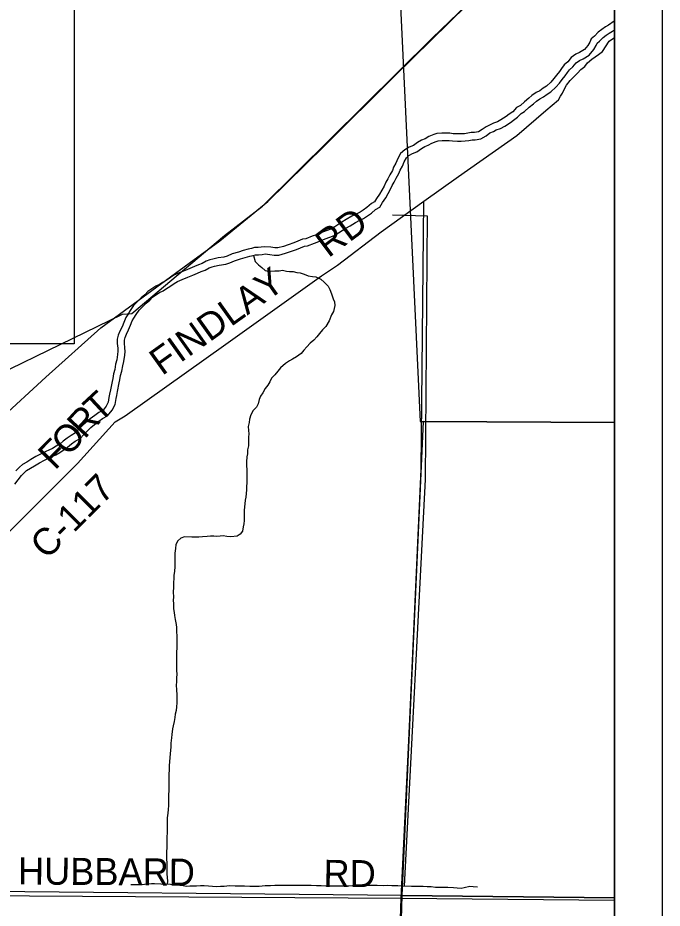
# Model space of a CAD drawing. Extents: x 0 to 34, y 0 to 22.
# Drawn here: x 7.646 to 9, y 14.995 to 16.867 of the extents above; entities that cross this region are included whole.
import ezdxf

# ---------------------------------------------------------------- set-up
doc = ezdxf.new("R2010")
doc.units = 0
for name, color, linetype in [('GM_X_City_Street', 7, 'Continuous'), ('GM_X_County_Road', 7, 'Continuous'), ('GM_X_County_Road_Text', 7, 'Continuous'), ('GM_X_Major_River', 7, 'Continuous'), ('GM_X_Minor_River', 7, 'Continuous'), ('GM_X_Rail_Line', 7, 'Continuous'), ('GM_X_State_Route', 7, 'Continuous'), ('GM_X_Township_Road', 7, 'Continuous'), ('GM_X_US_Route', 7, 'Continuous'), ('SH_Cut_Line', 7, 'Continuous'), ('SH_Data', 7, 'Continuous'), ('SH_Text', 7, 'Continuous')]:
    doc.layers.add(name, color=color, linetype=linetype)

msp = doc.modelspace()

# ---------------------------------------------------------------- linework, layer by layer
at = {"layer": 'GM_X_City_Street'}
for points in [[(8.9, 16.0164), (8.9, 16.9842), (8.447, 16.9667), (8.4914, 16.018), (8.4978, 16.0183)], [(8.9, 15.0171), (8.9, 16.0164), (8.4978, 16.0183), (8.4534, 15.0216)], [(7.4233, 14.1), (8.4275, 14.1), (8.4534, 15.0216), (7.4447, 15.0317), (7.4446, 15.029)], [(8.4275, 14.1), (8.9, 14.1), (8.9, 15.0171), (8.4534, 15.0216)]]:
    msp.add_lwpolyline(points, close=True, dxfattribs=at)
at = {"layer": 'GM_X_County_Road'}
for points in [[(7.6294, 15.7881), (7.7715, 15.9302), (7.8512, 16.0176), (7.8717, 16.0305), (8.0836, 16.1807), (8.2844, 16.3244), (8.3178, 16.3472), (8.4097, 16.4167), (8.4993, 16.4817), (8.5722, 16.5334), (8.6944, 16.6193), (8.7559, 16.6721), (8.7825, 16.6942), (8.7867, 16.7025), (8.7905, 16.7086), (8.7951, 16.7177), (8.7992, 16.7253), (8.8068, 16.7348), (8.8224, 16.7504), (8.8292, 16.758), (8.8376, 16.7645), (8.8433, 16.7721), (8.8524, 16.7801), (8.8665, 16.7899), (8.8744, 16.7964), (8.8885, 16.8177), (8.9, 16.8254)], [(7.447, 15.0225), (8.4514, 15.0162), (8.9, 15.0119)]]:
    msp.add_lwpolyline(points, dxfattribs=at)
at = {"layer": 'GM_X_Major_River'}
for points in [[(8.9, 16.8615), (8.8991, 16.8599), (8.8874, 16.8515), (8.8806, 16.8477), (8.8734, 16.8427), (8.8658, 16.8366), (8.8575, 16.8286), (8.8511, 16.8225), (8.8477, 16.8156), (8.8439, 16.8088), (8.8367, 16.8004), (8.8265, 16.7943), (8.8186, 16.7904), (8.8091, 16.7832), (8.8016, 16.7744), (8.7944, 16.7683), (8.7883, 16.7607), (8.7842, 16.7538), (8.7778, 16.7466), (8.7725, 16.739), (8.7661, 16.7317), (8.757, 16.7233), (8.7502, 16.7187), (8.743, 16.7137), (8.735, 16.7099), (8.7263, 16.7034), (8.7199, 16.6981), (8.7108, 16.6904), (8.7021, 16.6824), (8.6942, 16.6782), (8.6862, 16.6694), (8.6787, 16.6644), (8.6722, 16.6595), (8.6612, 16.6522), (8.6541, 16.648), (8.6457, 16.6453), (8.6389, 16.6418), (8.6306, 16.638), (8.6222, 16.6319), (8.6139, 16.6273), (8.6056, 16.6257), (8.5991, 16.6257), (8.5915, 16.6241), (8.5847, 16.6233), (8.5771, 16.6229), (8.5707, 16.6229), (8.5612, 16.6232), (8.5536, 16.6243), (8.5373, 16.6242), (8.5267, 16.6234), (8.5202, 16.6215), (8.5096, 16.6172), (8.502, 16.6126), (8.4945, 16.6099), (8.4861, 16.6046), (8.4774, 16.5988), (8.4687, 16.595), (8.4592, 16.5896), (8.4505, 16.582), (8.4445, 16.571), (8.4408, 16.5615), (8.4359, 16.5531), (8.4332, 16.5462), (8.4279, 16.5367), (8.4238, 16.5287), (8.4193, 16.5215), (8.4159, 16.5131), (8.411, 16.5047), (8.4065, 16.4964), (8.4001, 16.4872), (8.3959, 16.4804), (8.3891, 16.4765), (8.3796, 16.4681), (8.3721, 16.4624)], [(8.3812, 16.4503), (8.3893, 16.4564), (8.3979, 16.4641), (8.4068, 16.4691), (8.4128, 16.4789), (8.4194, 16.4884), (8.4242, 16.4973), (8.4295, 16.5064), (8.4328, 16.5146), (8.437, 16.5212), (8.4413, 16.5296), (8.447, 16.5398), (8.4496, 16.5465), (8.4544, 16.5548), (8.4583, 16.5645), (8.4626, 16.5724), (8.4681, 16.5772), (8.4755, 16.5814), (8.4847, 16.5855), (8.4944, 16.5919), (8.5012, 16.5963), (8.5086, 16.5989), (8.5164, 16.6036), (8.5252, 16.6071), (8.5294, 16.6084), (8.5379, 16.6091), (8.5525, 16.6091), (8.5598, 16.6081), (8.5704, 16.6077), (8.5776, 16.6077), (8.586, 16.6082), (8.5939, 16.6091), (8.6007, 16.6105), (8.607, 16.6106), (8.6191, 16.6128), (8.6304, 16.6191), (8.6383, 16.6249), (8.6455, 16.6282), (8.6515, 16.6312), (8.6603, 16.6341), (8.6693, 16.6393), (8.6811, 16.6471), (8.6875, 16.6521), (8.6962, 16.6578), (8.7036, 16.666), (8.7109, 16.6699), (8.7208, 16.679), (8.7296, 16.6864), (8.7357, 16.6915), (8.7429, 16.6969), (8.7506, 16.7006), (8.7587, 16.7062), (8.7664, 16.7114), (8.7769, 16.7211), (8.7844, 16.7296), (8.7897, 16.7372), (8.7964, 16.7448), (8.8008, 16.752), (8.8053, 16.7577), (8.8123, 16.7636), (8.8196, 16.7721), (8.8266, 16.7775), (8.8337, 16.7809), (8.8467, 16.7887), (8.8565, 16.8001), (8.8611, 16.8086), (8.8635, 16.8134), (8.868, 16.8176), (8.8759, 16.8252), (8.8825, 16.8306), (8.8886, 16.8348), (8.8956, 16.8387), (8.9, 16.8419)], [(8.3721, 16.4624), (8.3656, 16.4582), (8.3584, 16.4551), (8.3482, 16.4501), (8.3365, 16.4429), (8.3274, 16.4375), (8.3122, 16.4275), (8.3043, 16.4229), (8.2963, 16.4199), (8.2865, 16.416), (8.2736, 16.4106), (8.2649, 16.4076), (8.2513, 16.4025), (8.2448, 16.4014), (8.235, 16.3975), (8.2266, 16.3941), (8.2141, 16.3898), (8.2043, 16.3864), (8.1929, 16.3833), (8.1861, 16.3832), (8.1781, 16.3847), (8.1656, 16.3858), (8.1576, 16.3846), (8.1511, 16.3838), (8.1439, 16.3838), (8.1375, 16.3822), (8.1303, 16.3807), (8.1197, 16.3779), (8.1098, 16.3745), (8.0966, 16.3706), (8.086, 16.366), (8.0795, 16.3637), (8.067, 16.3621), (8.0564, 16.3598), (8.0499, 16.3582), (8.042, 16.3551), (8.034, 16.3505), (8.0261, 16.3478), (8.0177, 16.3444), (8.0079, 16.3402), (7.9977, 16.3359), (7.9852, 16.3309), (7.9745, 16.3256), (7.967, 16.321), (7.9579, 16.3148), (7.9507, 16.3106), (7.9443, 16.3064), (7.9367, 16.303), (7.9303, 16.2987), (7.9197, 16.2915), (7.9132, 16.2846), (7.9057, 16.2785), (7.8894, 16.2621), (7.8822, 16.2514), (7.8773, 16.2434), (7.8732, 16.2366), (7.8691, 16.2263), (7.8653, 16.2172), (7.8608, 16.208), (7.8574, 16.1997), (7.8552, 16.1917), (7.8552, 16.1822), (7.8564, 16.1723), (7.8564, 16.1659), (7.856, 16.159), (7.8542, 16.1476), (7.8519, 16.1385), (7.8501, 16.1275), (7.8475, 16.1184), (7.846, 16.1089), (7.8445, 16.1024), (7.8411, 16.0846), (7.8393, 16.0758), (7.8378, 16.069), (7.8363, 16.0587), (7.8322, 16.0504), (7.8254, 16.0423), (7.8163, 16.0374), (7.808, 16.0312), (7.7981, 16.024), (7.7898, 16.0171), (7.7815, 16.0091), (7.7739, 16.0015), (7.7675, 15.9946), (7.7584, 15.9892), (7.7501, 15.9831), (7.7418, 15.9766), (7.7353, 15.9716), (7.727, 15.9663), (7.7194, 15.9617), (7.7115, 15.9582), (7.705, 15.9552), (7.6956, 15.9502), (7.6846, 15.9444), (7.674, 15.9383), (7.6653, 15.9329), (7.6562, 15.9276), (7.6498, 15.9222), (7.6426, 15.9146)], [(7.64, 15.8867), (7.6473, 15.8957), (7.6542, 15.9048), (7.6602, 15.9112), (7.6649, 15.9151), (7.6731, 15.92), (7.6818, 15.9253), (7.6919, 15.9311), (7.7026, 15.9368), (7.7118, 15.9416), (7.7178, 15.9444), (7.7264, 15.9482), (7.735, 15.9534), (7.7441, 15.9592), (7.7511, 15.9646), (7.7592, 15.971), (7.7668, 15.9766), (7.7771, 15.9826), (7.7848, 15.9909), (7.7921, 15.9983), (7.7999, 16.0058), (7.8075, 16.012), (7.8169, 16.019), (7.8244, 16.0246), (7.8351, 16.0304), (7.8449, 16.042), (7.851, 16.0542), (7.8527, 16.0663), (7.8541, 16.0726), (7.856, 16.0816), (7.8593, 16.0993), (7.8609, 16.106), (7.8623, 16.1151), (7.8649, 16.1241), (7.8668, 16.1355), (7.869, 16.1446), (7.8711, 16.1574), (7.8716, 16.1655), (7.8715, 16.1733), (7.8703, 16.1831), (7.8703, 16.1896), (7.8718, 16.1948), (7.8746, 16.2018), (7.8791, 16.2109), (7.8831, 16.2206), (7.8868, 16.2298), (7.8903, 16.2355), (7.895, 16.2432), (7.9012, 16.2524), (7.9158, 16.2672), (7.9236, 16.2735), (7.9296, 16.2799), (7.9387, 16.2861), (7.944, 16.2896), (7.9516, 16.2931), (7.9587, 16.2977), (7.966, 16.302), (7.9751, 16.3082), (7.9819, 16.3123), (7.9914, 16.3171), (8.0034, 16.3219), (8.0138, 16.3262), (8.0236, 16.3304), (8.0314, 16.3336), (8.0403, 16.3367), (8.0485, 16.3414), (8.0545, 16.3437), (8.0598, 16.345), (8.0696, 16.3471), (8.0831, 16.3489), (8.0915, 16.3519), (8.1017, 16.3563), (8.1145, 16.36), (8.1241, 16.3634), (8.1338, 16.3659), (8.1409, 16.3674), (8.1458, 16.3686), (8.1521, 16.3686), (8.1596, 16.3696), (8.166, 16.3705), (8.1761, 16.3697), (8.1847, 16.3681), (8.195, 16.3681), (8.2088, 16.3719), (8.2191, 16.3755), (8.232, 16.3799), (8.2406, 16.3835), (8.249, 16.3867), (8.2553, 16.3879), (8.27, 16.3933), (8.2791, 16.3965), (8.2922, 16.402), (8.3018, 16.4057), (8.3109, 16.4092), (8.3202, 16.4146), (8.3354, 16.4246), (8.3443, 16.4299), (8.3555, 16.4368), (8.3647, 16.4413), (8.3728, 16.4448), (8.3812, 16.4503)]]:
    msp.add_lwpolyline(points, dxfattribs=at)
at = {"layer": 'GM_X_Minor_River'}
for p, q in [((8.4334, 16.4525), (8.5064, 16.4504)), ((8.5064, 16.4504), (8.5023, 15.8958)), ((8.5023, 15.8962), (8.4583, 15.0418))]:
    msp.add_line(p, q, dxfattribs=at)
for points in [[(8.1417, 16.3676), (8.1448, 16.3545), (8.152, 16.3474), (8.1593, 16.3421), (8.1661, 16.3357), (8.1733, 16.3346), (8.1866, 16.335), (8.1954, 16.3351), (8.2022, 16.3362), (8.2109, 16.3344), (8.2174, 16.3337), (8.225, 16.3337), (8.2329, 16.3318), (8.2398, 16.3311), (8.2481, 16.3281), (8.2565, 16.3244), (8.2652, 16.3233), (8.2724, 16.3222), (8.2827, 16.3177), (8.2899, 16.3109), (8.2983, 16.3026), (8.3021, 16.2958), (8.3052, 16.2867), (8.3087, 16.2761), (8.3117, 16.2696), (8.3125, 16.262), (8.3095, 16.2495), (8.3054, 16.2423), (8.3005, 16.2297), (8.2937, 16.2183), (8.2865, 16.2107), (8.2801, 16.2034), (8.2744, 16.1966), (8.268, 16.1893), (8.2604, 16.1832), (8.2536, 16.1752), (8.2472, 16.1679), (8.2419, 16.1611), (8.2321, 16.1542), (8.2234, 16.1496), (8.2169, 16.1461), (8.2086, 16.1404), (8.198, 16.1309), (8.1924, 16.124), (8.1863, 16.1164), (8.1795, 16.1091), (8.1761, 16.1019), (8.1716, 16.0947), (8.1659, 16.0874), (8.1614, 16.0787), (8.1565, 16.0718), (8.1535, 16.0642), (8.1516, 16.0551), (8.1479, 16.0482), (8.1407, 16.0414), (8.1358, 16.0322), (8.1332, 16.0231), (8.1321, 16.0159), (8.1306, 16.0079), (8.131, 15.9995), (8.1314, 15.9923), (8.131, 15.9855), (8.1311, 15.9737), (8.1307, 15.9669), (8.1292, 15.9585), (8.1289, 15.9506), (8.1278, 15.9437), (8.1271, 15.9335), (8.1272, 15.9092), (8.1276, 15.9023), (8.1272, 15.8898), (8.1269, 15.8811), (8.1265, 15.8746), (8.1258, 15.867), (8.1251, 15.8591), (8.124, 15.8526), (8.1232, 15.845), (8.1221, 15.8317), (8.1222, 15.8169), (8.1218, 15.8101), (8.1211, 15.8032), (8.12, 15.7968), (8.1181, 15.788), (8.1136, 15.7812), (8.1072, 15.7773), (8.0939, 15.7761), (8.0855, 15.7765), (8.078, 15.7776), (8.0715, 15.7775), (8.0647, 15.7767), (8.0582, 15.7771), (8.051, 15.7771), (8.0442, 15.7766), (8.0343, 15.7758), (8.0264, 15.7754), (8.0119, 15.7753), (7.9968, 15.776), (7.9892, 15.7729), (7.9824, 15.7676), (7.9786, 15.76), (7.9775, 15.7516)], [(7.9775, 15.7516), (7.976, 15.7417), (7.9761, 15.7129), (7.9754, 15.7034), (7.9743, 15.6947), (7.9739, 15.6882), (7.9732, 15.6795), (7.9733, 15.67), (7.9729, 15.6593), (7.9733, 15.6499), (7.973, 15.6423), (7.9734, 15.6354), (7.9738, 15.6244), (7.9746, 15.6168), (7.9754, 15.6104), (7.9769, 15.6024), (7.9789, 15.5918), (7.9797, 15.585), (7.9801, 15.5751), (7.9805, 15.5687), (7.9805, 15.5607), (7.9802, 15.5527), (7.9802, 15.5447), (7.9799, 15.5314), (7.9799, 15.5189), (7.9796, 15.5083), (7.9796, 15.5018), (7.98, 15.4954), (7.9804, 15.4867), (7.9801, 15.4802), (7.9801, 15.4715), (7.9794, 15.4631), (7.9798, 15.4551), (7.9802, 15.443), (7.9806, 15.4354), (7.9806, 15.4267), (7.9799, 15.4183), (7.9788, 15.4107), (7.9773, 15.4031), (7.9762, 15.3963), (7.9747, 15.3875), (7.9729, 15.3788), (7.9717, 15.3723), (7.9699, 15.3602), (7.9692, 15.353), (7.9681, 15.342), (7.9677, 15.3336), (7.967, 15.3271), (7.9666, 15.3196), (7.9659, 15.312), (7.9648, 15.3025), (7.9644, 15.2949), (7.9641, 15.2858), (7.9638, 15.277), (7.9634, 15.2702), (7.9635, 15.2523), (7.9635, 15.2429), (7.9632, 15.2334), (7.9628, 15.2227), (7.9629, 15.211), (7.9621, 15.2026), (7.9614, 15.195), (7.9603, 15.1851), (7.96, 15.1787), (7.96, 15.1582), (7.9593, 15.14), (7.9594, 15.1221), (7.9591, 15.1141), (7.9592, 15.0743), (7.9596, 15.0674), (7.9604, 15.0595), (7.9608, 15.0523), (7.9605, 15.0458)], [(7.9605, 15.0458), (7.9559, 15.0446), (7.9468, 15.0457), (7.9339, 15.0464), (7.9271, 15.0464), (7.9127, 15.0448), (7.9054, 15.0444), (7.8914, 15.0443), (7.8842, 15.0446)], [(8.612, 15.0394), (8.6029, 15.0401), (8.5957, 15.0408), (8.5843, 15.0377), (8.5775, 15.0369), (8.5695, 15.0373), (8.5619, 15.038), (8.5494, 15.0387), (8.5388, 15.0386), (8.5308, 15.039), (8.5236, 15.0389), (8.5145, 15.04), (8.5061, 15.04), (8.4978, 15.0407), (8.4891, 15.0406), (8.4796, 15.0406), (8.4731, 15.0409), (8.4541, 15.0416), (8.445, 15.0419), (8.4382, 15.0419), (8.4318, 15.0422), (8.4238, 15.0426), (8.4139, 15.0425), (8.4014, 15.0428), (8.3934, 15.0432), (8.3858, 15.0431), (8.3737, 15.0427), (8.3672, 15.0426), (8.3593, 15.0422), (8.3498, 15.0422), (8.3418, 15.0417), (8.3232, 15.0417), (8.3111, 15.0412), (8.3046, 15.0416), (8.2933, 15.0415), (8.2834, 15.0422), (8.2739, 15.0422), (8.2629, 15.0429), (8.2424, 15.0427), (8.2341, 15.0431), (8.2196, 15.043), (8.2094, 15.0426), (8.1965, 15.0429), (8.1866, 15.0428), (8.1775, 15.0424), (8.1658, 15.042), (8.1532, 15.0411), (8.1445, 15.0411), (8.1339, 15.0407), (8.1229, 15.0414), (8.1096, 15.0417), (8.1028, 15.0416), (8.091, 15.0419), (8.08, 15.0411), (8.072, 15.0407), (8.0633, 15.0403), (8.0553, 15.0406), (8.047, 15.0413), (8.0379, 15.042), (8.0299, 15.042), (8.022, 15.0416), (8.0075, 15.0415), (7.9999, 15.0411), (7.9935, 15.0422), (7.9605, 15.0458)]]:
    msp.add_lwpolyline(points, dxfattribs=at)
at = {"layer": 'GM_X_Rail_Line'}
msp.add_lwpolyline([(7.4742, 16.0534), (7.8661, 16.2441), (7.8862, 16.2455), (8.0808, 16.409), (8.1603, 16.4709), (8.5168, 16.8244), (8.6624, 16.9647), (8.9, 17.2081)], dxfattribs=at)
at = {"layer": 'GM_X_State_Route'}
msp.add_lwpolyline([(7.4722, 15.887), (7.5101, 15.9321), (7.7055, 16.1117), (7.8205, 16.2154), (8.0065, 16.3511), (8.0705, 16.3981), (8.1716, 16.4806), (8.2905, 16.5979), (8.4388, 16.7459), (8.5901, 16.8939), (8.6621, 16.9631), (8.9, 17.2081)], dxfattribs=at)
at = {"layer": 'GM_X_Township_Road'}
for points in [[(8.4703, 15.4072), (8.4935, 15.918), (8.4993, 16.4817)], [(8.4514, 15.0162), (8.4657, 15.3038), (8.4703, 15.4072)], [(8.4384, 14.5129), (8.4459, 14.8437), (8.4514, 15.0162)]]:
    msp.add_lwpolyline(points, dxfattribs=at)
at = {"layer": 'GM_X_US_Route'}
msp.add_lwpolyline([(8.9, 14.5091), (8.9, 20.9)], dxfattribs=at)
at = {"layer": 'SH_Cut_Line'}
msp.add_lwpolyline([(8.9, 14.1), (8.9, 20.9)], dxfattribs=at)
at = {"layer": 'SH_Data'}
for p, q in [((9, 21), (9, 14)), ((8.9, 20.9), (8.9, 14.1))]:
    msp.add_line(p, q, dxfattribs=at)
at = {"layer": 'SH_Text'}
msp.add_lwpolyline([(5.7647, 16.9319), (7.7647, 16.9319), (7.7647, 16.1819), (5.7647, 16.1819)], close=True, dxfattribs=at)

# ---------------------------------------------------------------- texts
at = {"layer": 'GM_X_County_Road_Text'}
for s, height, rotation, p in [('RD', 0.05682, 36.7812, (8.2988, 16.3611)), ('FINDLAY', 0.05682, 35.4665, (7.9495, 16.1135)), ('T', 0.0568, 42.8964, (7.8174, 16.0135)), ('R', 0.0568, 47.45, (7.7867, 15.9799)), ('O', 0.0568, 47.0338, (7.7523, 15.943)), ('F', 0.0568, 45.3662, (7.7242, 15.9144)), ('C-117', 0.05682, 45, (7.7072, 15.7262)), ('HUBBARD', 0.05682, 359.5779, (7.6467, 15.0451)), ('RD', 0.05682, 359.5045, (8.2884, 15.0401))]:
    msp.add_text(s, height=height, rotation=rotation, dxfattribs=at).set_placement(p)

doc.saveas('drawing.dxf')
